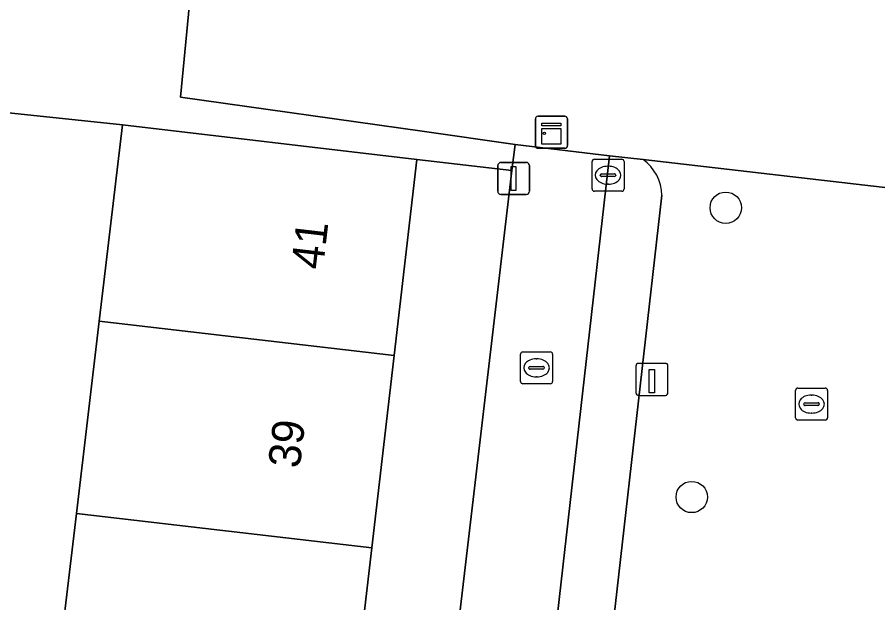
# Model space of a CAD drawing. Extents: x 161241 to 161758, y 384138 to 384885.
# Drawn here: x 161505.19 to 161532.09, y 384434.03 to 384452.33 of the extents above; entities that cross this region are included whole.
import ezdxf

# ---------------------------------------------------------------- set-up
doc = ezdxf.new("R2010")
doc.units = 0
for name, color, linetype in [('IMGEO_Boom', 7, 'Continuous'), ('IMGEO_Erf', 7, 'Continuous'), ('IMGEO_Kast', 7, 'Continuous'), ('IMGEO_Kolk', 7, 'Continuous'), ('IMGEO_Laadpaal', 7, 'Continuous'), ('IMGEO_Lichtmast', 7, 'Continuous'), ('IMGEO_Pand', 7, 'Continuous'), ('IMGEO_Pand_nummerreeks', 7, 'Continuous'), ('IMGEO_Parkeervlak_open', 7, 'Continuous'), ('IMGEO_Rijbaan_lokaal_open', 7, 'Continuous'), ('IMGEO_Rioolput', 7, 'Continuous'), ('IMGEO_Voetpad_open', 7, 'Continuous')]:
    doc.layers.add(name, color=color, linetype=linetype)

msp = doc.modelspace()

# ---------------------------------------------------------------- linework, layer by layer
at = {"layer": 'IMGEO_Boom'}
for centre in [(161527.339, 384446.375), (161526.276, 384437.337)]:
    msp.add_circle(centre, 0.489, dxfattribs=at)
at = {"layer": 'IMGEO_Erf'}
for points in [[(161513.81, 384486.25), (161510.292, 384449.829), (161517.847, 384448.768), (161520.752, 384448.346), (161523.706, 384448.001), (161524.754, 384447.882), (161542.574, 384445.815), (161535.519, 384449.439), (161535.215, 384448.848), (161533.998, 384449.45), (161533.842, 384449.528), (161532.616, 384450.135), (161533.54, 384452.19), (161525.753, 384456.145)], [(161497.509, 384431.003), (161506.232, 384429.97), (161506.33, 384430.8), (161507.045, 384436.823), (161507.757, 384442.83), (161507.902, 384444.052), (161508.484, 384448.961), (161498.29, 384450.04)], [(161500, 384419.47), (161517.124, 384417.504), (161520.657, 384447.535), (161517.687, 384447.884), (161516.973, 384441.758), (161516.273, 384435.748), (161515.556, 384429.595), (161512.877, 384429.943), (161511.936, 384422.181), (161505.541, 384422.92), (161505.583, 384423.539), (161496.808, 384424.548)]]:
    msp.add_lwpolyline(points, dxfattribs=at)
at = {"layer": 'IMGEO_Kast'}
for p, q in [((161521.392, 384448.307), (161521.392, 384449.148)), ((161521.392, 384449.148), (161521.392, 384448.307)), ((161521.467, 384449.232), (161522.308, 384449.232)), ((161522.308, 384449.232), (161521.467, 384449.232)), ((161522.392, 384449.157), (161522.392, 384448.316)), ((161522.392, 384448.316), (161522.392, 384449.157)), ((161522.317, 384448.232), (161521.476, 384448.232)), ((161521.476, 384448.232), (161522.317, 384448.232))]:
    msp.add_line(p, q, dxfattribs=at)
for points in [[(161521.587, 384449.022), (161522.187, 384449.022), (161522.187, 384448.937), (161521.587, 384448.937), (161521.587, 384449.022)], [(161521.587, 384448.847), (161522.187, 384448.847), (161522.187, 384448.358), (161521.587, 384448.358), (161521.587, 384448.847)]]:
    msp.add_lwpolyline(points, dxfattribs=at)
msp.add_circle((161521.671, 384448.696), 0.0377, dxfattribs=at)
for centre, start, end in [((161521.47, 384449.154), 92.4484, 184.2845), ((161521.47, 384449.154), 92.4484, 184.2845), ((161522.314, 384449.154), 2.4484, 94.2845), ((161522.314, 384449.154), 2.4484, 94.2845), ((161521.47, 384448.31), 182.4484, 274.2845), ((161521.47, 384448.31), 182.4484, 274.2845), ((161522.314, 384448.31), 272.4484, 4.2845), ((161522.314, 384448.31), 272.4484, 4.2845)]:
    msp.add_arc(centre, 0.0779, start, end, dxfattribs=at)
at = {"layer": 'IMGEO_Kolk'}
for p, q in [((161520.925, 384440.947), (161520.925, 384441.799)), ((161521, 384441.873), (161521.852, 384441.873)), ((161521.926, 384441.799), (161521.926, 384440.947)), ((161521.413, 384441.653), (161521.438, 384441.653)), ((161521.184, 384441.367), (161521.184, 384441.379)), ((161521.622, 384441.33), (161521.224, 384441.33)), ((161521.227, 384441.416), (161521.625, 384441.416)), ((161521.668, 384441.379), (161521.668, 384441.367)), ((161521.436, 384441.093), (161521.411, 384441.093)), ((161521.852, 384440.873), (161521, 384440.873)), ((161529.595, 384440.74), (161530.447, 384440.74)), ((161529.52, 384439.814), (161529.52, 384440.666)), ((161530.008, 384440.52), (161530.033, 384440.52)), ((161530.521, 384440.666), (161530.521, 384439.814)), ((161529.779, 384440.234), (161529.779, 384440.246)), ((161530.217, 384440.197), (161529.819, 384440.197)), ((161529.822, 384440.283), (161530.22, 384440.283)), ((161530.263, 384440.246), (161530.263, 384440.234)), ((161530.031, 384439.96), (161530.006, 384439.96)), ((161530.447, 384439.74), (161529.595, 384439.74))]:
    msp.add_line(p, q, dxfattribs=at)
for points in [[(161520.925, 384440.947), (161520.925, 384441.799)], [(161521, 384441.873), (161521.852, 384441.873)], [(161521.926, 384441.799), (161521.926, 384440.947)], [(161521.852, 384440.873), (161521, 384440.873)], [(161529.595, 384440.74), (161530.447, 384440.74)], [(161529.52, 384439.814), (161529.52, 384440.666)], [(161530.521, 384440.666), (161530.521, 384439.814)], [(161530.447, 384439.74), (161529.595, 384439.74)]]:
    msp.add_lwpolyline(points, dxfattribs=at)
for centre, radius, start, end in [((161521.002, 384441.797), 0.0765, 91.552, 178.448), ((161521.002, 384441.797), 0.0765, 91.552, 178.448), ((161521.85, 384441.797), 0.0765, 1.552, 88.448), ((161521.85, 384441.797), 0.0765, 1.552, 88.448), ((161521.224, 384441.376), 0.0403, 85.8775, 175.7526), ((161521.221, 384441.366), 0.0366, 178.938, 274.7102), ((161521.625, 384441.373), 0.043, 264.8664, 352.4533), ((161521.629, 384441.378), 0.0386, 1.7309, 96.639), ((161521.002, 384440.949), 0.0765, 181.552, 268.448), ((161521.002, 384440.949), 0.0765, 181.552, 268.448), ((161521.85, 384440.949), 0.0765, 271.552, 358.448), ((161521.85, 384440.949), 0.0765, 271.552, 358.448), ((161529.597, 384440.664), 0.0765, 91.552, 178.448), ((161529.597, 384440.664), 0.0765, 91.552, 178.448), ((161530.445, 384440.664), 0.0765, 1.552, 88.448), ((161530.445, 384440.664), 0.0765, 1.552, 88.448), ((161529.819, 384440.243), 0.0403, 85.8775, 175.7526), ((161529.816, 384440.233), 0.0366, 178.938, 274.7102), ((161530.22, 384440.24), 0.043, 264.8664, 352.4533), ((161530.224, 384440.245), 0.0386, 1.7309, 96.639), ((161529.597, 384439.816), 0.0765, 181.552, 268.448), ((161529.597, 384439.816), 0.0765, 181.552, 268.448), ((161530.445, 384439.816), 0.0765, 271.552, 358.448), ((161530.445, 384439.816), 0.0765, 271.552, 358.448)]:
    msp.add_arc(centre, radius, start, end, dxfattribs=at)
for centre, major_axis, ratio, start_param, end_param in [((161521.412, 384441.373), (-0.387, 0.002), 0.722429, 4.712389, 7.853982), ((161521.437, 384441.373), (-0.39, 0.002), 0.717154, 1.570796, 4.712389), ((161530.007, 384440.24), (-0.387, 0.002), 0.722429, 4.712389, 7.853982), ((161530.032, 384440.24), (-0.39, 0.002), 0.717154, 1.570796, 4.712389)]:
    msp.add_ellipse(centre, major_axis=major_axis, ratio=ratio, start_param=start_param, end_param=end_param, dxfattribs=at)
at = {"layer": 'IMGEO_Laadpaal'}
for p, q in [((161525.449, 384441.513), (161524.608, 384441.513)), ((161525.449, 384441.513), (161524.608, 384441.513)), ((161524.533, 384441.429), (161524.533, 384440.588)), ((161524.533, 384441.429), (161524.533, 384440.588)), ((161525.533, 384440.597), (161525.533, 384441.438)), ((161525.533, 384440.597), (161525.533, 384441.438)), ((161524.617, 384440.513), (161525.458, 384440.513)), ((161524.617, 384440.513), (161525.458, 384440.513))]:
    msp.add_line(p, q, dxfattribs=at)
msp.add_lwpolyline([(161524.948, 384441.326), (161525.108, 384441.326), (161525.108, 384440.593), (161524.948, 384440.593), (161524.948, 384441.326)], dxfattribs=at)
for centre, start, end in [((161524.611, 384441.435), 92.4484, 184.2845), ((161524.611, 384441.435), 92.4484, 184.2845), ((161525.455, 384441.435), 2.4484, 94.2845), ((161525.455, 384441.435), 2.4484, 94.2845), ((161524.611, 384440.591), 182.4484, 274.2845), ((161524.611, 384440.591), 182.4484, 274.2845), ((161525.455, 384440.591), 272.4484, 4.2845), ((161525.455, 384440.591), 272.4484, 4.2845)]:
    msp.add_arc(centre, 0.0779, start, end, dxfattribs=at)
at = {"layer": 'IMGEO_Lichtmast'}
for p, q in [((161520.312, 384447.791), (161521.102, 384447.791)), ((161521.102, 384447.791), (161520.312, 384447.791)), ((161520.212, 384446.891), (161520.212, 384447.691)), ((161520.212, 384447.691), (161520.212, 384446.891)), ((161521.202, 384447.691), (161521.202, 384446.891)), ((161521.202, 384446.891), (161521.202, 384447.691)), ((161521.102, 384446.791), (161520.312, 384446.791)), ((161520.312, 384446.791), (161521.102, 384446.791))]:
    msp.add_line(p, q, dxfattribs=at)
msp.add_lwpolyline([(161520.632, 384447.666), (161520.782, 384447.666), (161520.782, 384446.916), (161520.632, 384446.916), (161520.632, 384447.666)], dxfattribs=at)
for centre, start, end in [((161520.312, 384447.691), 90, 180), ((161520.312, 384447.691), 90, 180), ((161521.102, 384447.691), 0, 90), ((161521.102, 384447.691), 360, 90), ((161520.312, 384446.891), 180, 270), ((161520.312, 384446.891), 180, 270), ((161521.102, 384446.891), 270, 0), ((161521.102, 384446.891), 270, 0)]:
    msp.add_arc(centre, 0.1, start, end, dxfattribs=at)
at = {"layer": 'IMGEO_Pand'}
for points in [[(161516.973, 384441.758), (161517.687, 384447.884), (161508.484, 384448.961), (161507.902, 384444.052), (161507.757, 384442.83)], [(161516.273, 384435.748), (161516.973, 384441.758), (161507.757, 384442.83), (161507.045, 384436.823)], [(161507.045, 384436.823), (161506.33, 384430.8), (161512.877, 384429.943), (161515.556, 384429.595), (161516.273, 384435.748)]]:
    msp.add_lwpolyline(points, close=True, dxfattribs=at)
at = {"layer": 'IMGEO_Parkeervlak_open'}
for points in [[(161524.754, 384447.882), (161523.706, 384448.001), (161521.24, 384426.245)], [(161523.271, 384428.499), (161525.345, 384446.763)]]:
    msp.add_lwpolyline(points, dxfattribs=at)
msp.add_arc((161523.914, 384446.723), 1.432, 1.6164, 54.0651, dxfattribs=at)
at = {"layer": 'IMGEO_Rijbaan_lokaal_open'}
for points in [[(161469.103, 384453.506), (161468.649, 384449.709), (161468.535, 384448.685), (161474.948, 384448.66), (161475.421, 384452.824), (161495.914, 384450.374), (161498.29, 384450.04), (161508.484, 384448.961), (161517.687, 384447.884), (161520.657, 384447.535), (161520.752, 384448.346), (161517.847, 384448.768), (161510.292, 384449.829), (161513.81, 384486.25)], [(161521.24, 384426.245), (161523.706, 384448.001), (161520.752, 384448.346), (161520.657, 384447.535), (161517.124, 384417.504), (161516.896, 384415.376), (161520.867, 384414.919)]]:
    msp.add_lwpolyline(points, dxfattribs=at)
at = {"layer": 'IMGEO_Rioolput'}
for p, q in [((161523.159, 384446.964), (161523.159, 384447.816)), ((161523.234, 384447.89), (161524.086, 384447.89)), ((161524.16, 384447.816), (161524.16, 384446.964)), ((161523.461, 384447.433), (161523.859, 384447.433)), ((161523.647, 384447.67), (161523.672, 384447.67)), ((161523.418, 384447.384), (161523.418, 384447.396)), ((161523.856, 384447.347), (161523.458, 384447.347)), ((161523.902, 384447.396), (161523.902, 384447.384)), ((161524.086, 384446.89), (161523.234, 384446.89)), ((161523.67, 384447.11), (161523.645, 384447.11))]:
    msp.add_line(p, q, dxfattribs=at)
for points in [[(161523.159, 384446.964), (161523.159, 384447.816)], [(161523.234, 384447.89), (161524.086, 384447.89)], [(161524.16, 384447.816), (161524.16, 384446.964)], [(161524.086, 384446.89), (161523.234, 384446.89)]]:
    msp.add_lwpolyline(points, dxfattribs=at)
for centre, radius, start, end in [((161523.236, 384447.814), 0.0765, 91.552, 178.448), ((161523.236, 384447.814), 0.0765, 91.552, 178.448), ((161524.084, 384447.814), 0.0765, 1.552, 88.448), ((161524.084, 384447.814), 0.0765, 1.552, 88.448), ((161523.458, 384447.393), 0.0403, 85.8775, 175.7526), ((161523.863, 384447.395), 0.0386, 1.7309, 96.639), ((161523.455, 384447.383), 0.0366, 178.938, 274.7102), ((161523.859, 384447.39), 0.043, 264.8664, 352.4533), ((161523.236, 384446.966), 0.0765, 181.552, 268.448), ((161523.236, 384446.966), 0.0765, 181.552, 268.448), ((161524.084, 384446.966), 0.0765, 271.552, 358.448), ((161524.084, 384446.966), 0.0765, 271.552, 358.448)]:
    msp.add_arc(centre, radius, start, end, dxfattribs=at)
for centre, major_axis, ratio, start_param, end_param in [((161523.646, 384447.39), (-0.387, 0.002), 0.722429, 4.712389, 7.853982), ((161523.671, 384447.39), (-0.39, 0.002), 0.717154, 1.570796, 4.712389)]:
    msp.add_ellipse(centre, major_axis=major_axis, ratio=ratio, start_param=start_param, end_param=end_param, dxfattribs=at)
at = {"layer": 'IMGEO_Voetpad_open'}
for points in [[(161538.237, 384432.477), (161539.566, 384435.11), (161544.826, 384445.532), (161542.574, 384445.815), (161524.754, 384447.882)], [(161525.345, 384446.763), (161523.271, 384428.499)]]:
    msp.add_lwpolyline(points, dxfattribs=at)
msp.add_arc((161523.914, 384446.723), 1.432, 1.6164, 54.0651, dxfattribs=at)

# ---------------------------------------------------------------- texts
at = {"layer": 'IMGEO_Pand_nummerreeks'}
for s, p in [('41', (161514.746, 384444.418)), ('39', (161514.023, 384438.21))]:
    msp.add_text(s, height=1, rotation=83.354, dxfattribs=at).set_placement(p)

doc.saveas('drawing.dxf')
